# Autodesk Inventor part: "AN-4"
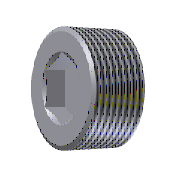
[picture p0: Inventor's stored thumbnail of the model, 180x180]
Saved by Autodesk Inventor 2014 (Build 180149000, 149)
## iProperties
IsCustomPart: 1
Created: 2009-11
Part Number: "AN-4"
Material: Copper,Cu
Description: Pressure plugs
Document SubType Name: Modeling
Designer: gaom
Standard Revision: 1
Manufacturer: DME
Language: en-US
Size Designation: "4"
Categories: <MemberInstance><Categories><Category DisplayName="Mold" InternalName="349578f2-f4d4-4954-8c09-8e99297a61c0" Mnemonic="MOLD"><Category DisplayName="Cooling Comp
Density: 8.96 g/cm^3
Appearance: Anodized - Dark Gray
Author: gaom
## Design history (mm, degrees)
body "Solid1"
revolve "Revolution1" stored, may be unused: angle "d11" = 90 deg
sketch "Sketch2"
  geometry: L1 (4.041, 0)-(2.021, -3.5); L2 (2.021, -3.5)-(-2.021, -3.5); L3 (-2.021, -3.5)-(-4.041, 0); L4 (-4.041, 0)-(-2.021, 3.5); L5 (-2.021, 3.5)-(2.021, 3.5); L6 (2.021, 3.5)-(4.041, 0); 2 further points
  constraints: 12 end point, 1 coincident, 1 horizontal alignment, 13 other
  dimensions: "d66" = 7 distance between parallel lines of L3 L6 (= SW)
extrude "Extrusion1" cut sketch "Sketch2" distance "d67" = 4.2 (= 0.6 x SW); taper "d68" = 0 deg
chamfer "Chamfer1" distance "d45" = 0.54159 (= 0.07737 x SW); stored, may be unused: second distance "d46" = 2, angle "d47" = 45 deg
thread "Thread1" dims "d52" = 10, "d53" = 0
sketch "Sketch1"
  geometry: L1 (0, -3.47)-(0, 20.819) reference; L2 (-4.041, 0)-(-6.579, 0); L3 (-6.579, 0)-(-6.266, 10); L4 (-6.266, 10)-(0, 10); L5 (-12.442, 17.349)-(-12.442, 1.349); L6 (-12.442, 1.349)-(-12.942, 1.349); L7 (-12.942, 1.349)-(-12.442, 17.349); L8 (0, 10)-(0, 4.2); L9 (-4.041, 0)-(-3.5, 0.313); L10 (-3.5, 0.313)-(-3.5, 4.2); L11 (-3.5, 4.2)-(0, 4.2); 1 further point
  constraints: 20 end point, 3 horizontal, 2 parallel, 2 perpendicular, 1 horizontal alignment, 1 point on line, 1 vertical
  dimensions: "d28" = 10 distance between parallel lines of L2 L4 (= L); "d29" = 13.157 diameter of L2.end L1 (= R_); "d57" = 16 distance of L5.start L5.end (= d100); "d58" = 0.5 distance of L5.end L6.end (= d101); "d62" = 4.2 distance between parallel lines of L2 L11 (= 0.6 x SW); "d63" = 7 diameter of L10 L1 (= SW); "d64" = 60 deg angle of L10 L9 (= d102); "d65" = 8.0829 diameter of L2.start L1 (= 1.1547 x SW)
other parameters: "SW" = 7 [user parameter; used in 6 equation terms], "L" = 10 [user parameter; used in 1 equation term], "d27" = 0, "R_" = 13.157 [user parameter; used in 1 equation term], "d49" = 0, "d61" = 0, "d100" = 16 [user parameter; used in 1 equation term], "d101" = 0.5 [user parameter; used in 1 equation term], "d102" = 60 deg [user parameter; used in 1 equation term]
